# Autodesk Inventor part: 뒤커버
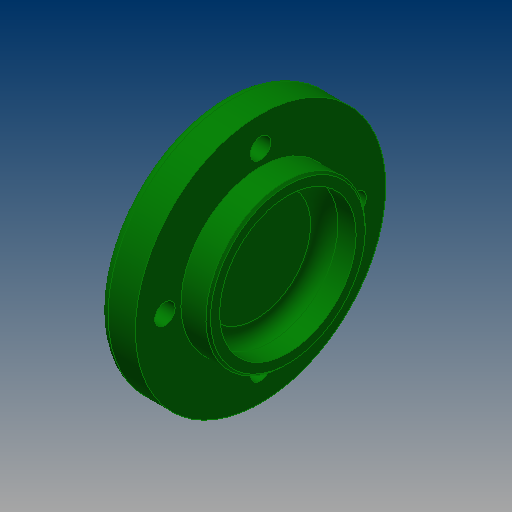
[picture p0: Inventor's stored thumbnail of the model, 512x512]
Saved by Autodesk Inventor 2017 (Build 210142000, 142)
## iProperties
Created: 2015-12
Part Number: 뒤커버
Material: 알루미늄 6061
Document SubType Name: Modeling
Designer: mduedu
Density: 2.71 g/cm^3
Appearance: 진녹색
Author: mduedu
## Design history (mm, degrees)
sketch "스케치1"
  geometry: L1 (0, 0)-(14, 0); L2 (14, 0)-(14, 17.5); L3 (14, 17.5)-(8, 17.5); L4 (8, 17.5)-(8, 27.5); L5 (8, 27.5)-(0, 27.5); L6 (0, 27.5)-(0, 0)
  constraints: 12 end point, 4 parallel, 1 horizontal, 1 perpendicular
  dimensions: "d0" = 14 distance between parallel lines of L2 L6; "d2" = 8 distance of L4.end L5.end; "d3" = 55 diameter of L5 L1; "d4" = 35 diameter of L3 L1
revolve "회전1" sketch "스케치1" stored, may be unused: angle "d5" = 90 deg
hole "구멍1" diameter "d8" = 30; stored, may be unused: countersink angle "d12" = 90 deg, drill point angle "d14" = 0 deg; dims "d9" = 6, "d10" = 4, "d11" = 2, "d13" = 7, "d39" = 10, "d40" = 10
fillet "모깎기3" dims "d38" = 2
fillet "모깎기4" dims "d41" = 3
chamfer "모따기2" distance "d42" = 0.5; stored, may be unused: second distance "d43" = 2, angle "d44" = 45 deg
sketch "스케치2" dims "d45" = 42
  geometry: 6 further points
  constraints: 2 vertical alignment, 1 coincident, 7 other
  dimensions: "d48" = 360 deg dimension on point (0, 0) point (0, 21) (derived)
sketch "스케치3"
  geometry: 4 further points
hole "구멍4" sketch "스케치3" at (-21, 0), (0, -21), (21, 0), (0, 21) diameter "d50" = 4.5; stored, may be unused: countersink angle "d54" = 90 deg, drill point angle "d56" = 0 deg; dims "d51" = 6, "d52" = 8, "d53" = 4.6, "d55" = 8
node "솔리드1"
